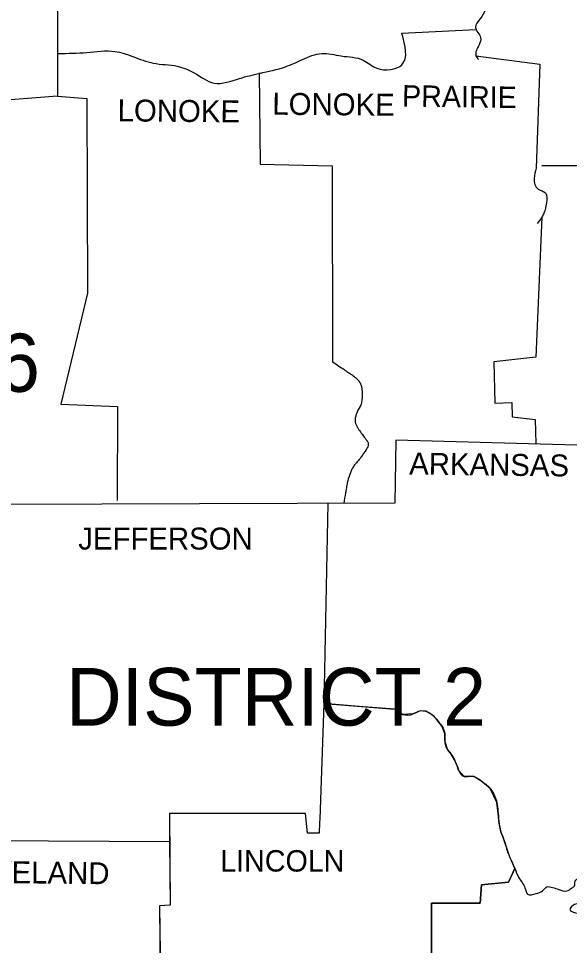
# Model space of a CAD drawing. Extents: x -31696 to 27919, y -8775 to 11152.
# Drawn here: x 13726 to 14782, y 6429 to 8206 of the extents above; entities that cross this region are included whole.
import ezdxf

# ---------------------------------------------------------------- set-up
doc = ezdxf.new("R2010")
doc.units = 0
for name, color, linetype in [('Level 1', 7, 'Continuous'), ('Level 2', 7, 'Continuous'), ('Level 3', 7, 'Continuous'), ('Level 48', 7, 'Continuous')]:
    doc.layers.add(name, color=color, linetype=linetype)

msp = doc.modelspace()

# ---------------------------------------------------------------- linework, layer by layer
at = {"layer": 'Level 1'}
for points in [[(13735.5, 10291.4), (13737.5, 10058.6), (13720.8, 10057.6), (13723.8, 9814), (13655.3, 9804.2), (13661.2, 9738.6), (13684.6, 9708.3), (13682.7, 9631), (13549.6, 9626.1), (13544.7, 9506.8), (13423.4, 9502.9), (13417.5, 9358), (13424.4, 9346.3), (13427.3, 9115.4), (13636.7, 9101.7), (13633.8, 8586.1), (13800.1, 8581.2), (13800.1, 8056.8), (13669, 8047), (13659.2, 7931.5), (13439.1, 7930.6)], [(15103.3, 8597.8), (15118, 8061.7), (14885.1, 8060.7), (14884.2, 8039.2), (14816.7, 8035.2), (14810.8, 7923.7), (14728.6, 7923.7)], [(14460.5, 8178.1), (14602.4, 8184.9)], [(14602.4, 8134.1), (14724.7, 8118.4), (14717.8, 7918.8)], [(14186.6, 8101.8), (14188.5, 7926.6), (14326.5, 7923.7), (14327.4, 7548)], [(13800.1, 8056.8), (13856.8, 8052.9), (13857.8, 7679.1), (13806.9, 7466.8), (13915.5, 7461.9), (13914.6, 7281.9)], [(14728.6, 7824.9), (14716.9, 7556.8), (14636.6, 7548), (14638.6, 7468.7), (14670.9, 7469.7), (14671.8, 7442.3), (14715.9, 7437.4), (14717.3, 7390.9)], [(14818.6, 7387.5), (14448.8, 7397.3), (14446.8, 7277), (13698.3, 7274)], [(14318.8, 7276.5), (14310.8, 6892.5), (14446.8, 6881.7)], [(14310.8, 6892.5), (14303, 6671.2)], [(14302.7, 6664.6), (14302, 6643.9), (14279.5, 6643.9), (14275.6, 6682.1), (14015.3, 6682.1), (14015.3, 6627.3)], [(13667, 6630.3), (14015.3, 6628.3)], [(14015.3, 6628.3), (14016.3, 6506), (13995.8, 6505), (14001.6, 6099)], [(14676.7, 6576.4), (14665, 6550), (14613.1, 6545.1), (14610.2, 6509.9), (14517.3, 6509.9), (14516.3, 6217.4)]]:
    msp.add_lwpolyline(points, dxfattribs=at)
for points in [[(14726.6, 8711.3), (14721.7, 8679), (14703.2, 8670.2), (14681.6, 8648.7), (14676.7, 8629.1), (14659.1, 8621.3), (14642.5, 8600.8), (14631.7, 8572.4), (14631.7, 8543), (14638.6, 8509.8), (14663, 8501), (14674.8, 8481.4), (14672.8, 8460.8), (14696.3, 8447.2), (14700.2, 8435.4), (14696.3, 8422.7), (14685.5, 8386.5), (14686.5, 8362), (14684.6, 8351.3), (14658.2, 8344.4), (14642.5, 8318), (14631.7, 8299.4), (14627.8, 8275), (14630.8, 8257.3), (14622.9, 8243.6), (14620, 8223.1), (14610.2, 8205.5), (14601.4, 8188.9), (14611.2, 8169.3), (14608.3, 8155.6), (14602.4, 8134.1), (14607.3, 8127.2)], [(13802, 8139), (13856.8, 8140.9), (13910.6, 8142.9), (13944.9, 8133.1), (13984, 8120.4), (14030, 8114.5), (14062.3, 8101.8), (14100.5, 8082.2), (14149.4, 8091), (14187.5, 8100.8), (14237.4, 8113.5), (14269.7, 8127.2), (14306.9, 8139), (14344.1, 8134.1), (14386.2, 8126.2), (14412.6, 8110.6), (14460.5, 8117.4), (14460.5, 8178.1)], [(14717.8, 7918.8), (14713.9, 7899.2), (14721.7, 7878.7), (14735.4, 7871.8), (14737.4, 7852.3), (14732.5, 7832.7), (14728.6, 7824.9), (14719.8, 7813.1)], [(14327.4, 7548), (14351.9, 7531.4), (14358.5, 7527), (14365, 7522.7), (14371.3, 7517.8), (14374.3, 7515), (14375.8, 7513.4), (14377.3, 7511.8), (14381.2, 7505.7), (14383.2, 7499.1), (14384, 7492.2), (14384.1, 7488.8), (14384.2, 7485.4), (14384.2, 7480.7), (14383.9, 7476), (14383.3, 7471.4), (14382.2, 7466.8), (14380.6, 7462.7), (14378.4, 7458.9), (14376.2, 7455.1), (14374.4, 7451.1), (14372.4, 7445.1), (14370.9, 7438.7), (14372.5, 7426.7), (14373.8, 7424.4), (14375.2, 7422.2), (14378.1, 7417.7), (14384.2, 7409.1), (14386.9, 7405.4), (14389.8, 7401.7), (14393.8, 7396.3), (14394.4, 7395.3), (14395, 7394.4), (14395.9, 7388.1), (14393.2, 7381.3), (14388.7, 7374.5), (14386.4, 7371.2), (14384.2, 7368), (14382, 7364.7), (14379.5, 7361.7), (14374.5, 7355.9), (14369.7, 7350), (14367.5, 7346.9), (14365.6, 7343.5), (14362.5, 7336.9), (14359.7, 7330.1), (14355.8, 7316.1), (14354, 7306.2), (14352.3, 7296.4), (14349.2, 7276.6)], [(14446.8, 6881.7), (14461.5, 6871.9), (14482, 6872.9), (14495.7, 6878.8), (14506.5, 6877.8), (14521.2, 6869), (14531, 6857.2), (14537.8, 6848.4), (14542.7, 6834.7), (14542.7, 6822), (14547.6, 6804.4), (14553.5, 6797.6), (14561.3, 6784.8), (14566.2, 6773.1), (14569.1, 6765.3), (14579.9, 6752.6), (14589.7, 6753.5), (14598.5, 6752.6), (14610.2, 6745.7), (14627.8, 6732), (14630.8, 6728.1), (14642.5, 6702.7), (14644.5, 6687), (14646.4, 6666.5), (14650.3, 6646.9), (14658.2, 6625.4), (14662.1, 6610.7), (14670.9, 6590.1), (14676.7, 6576.4), (14684.6, 6558.8), (14696.3, 6539.3), (14701.2, 6527.5), (14717.8, 6528.5), (14729.6, 6533.4), (14738.4, 6541.2), (14749.1, 6540.2), (14760.9, 6536.3), (14776.5, 6533.4), (14786.3, 6539.3), (14791.2, 6543.2), (14792.2, 6552), (14801, 6556.9), (14810.8, 6550), (14821.5, 6534.4), (14821.5, 6524.6), (14817.6, 6518.7), (14804.9, 6510.9), (14787.3, 6505), (14782.4, 6498.2), (14799, 6490.3), (14825.5, 6488.4), (14832.3, 6494.3), (14849.9, 6489.4), (14856.8, 6494.3), (14880.2, 6493.3), (14891, 6501.1), (14912.5, 6500.1), (14919.4, 6495.2), (14919.4, 6486.4), (14937, 6482.5), (14949.7, 6485.4), (14966.3, 6480.6), (14981, 6472.7), (14988.9, 6462), (14998.6, 6450.2), (15007.4, 6453.2), (15014.3, 6462), (15029, 6477.6), (15029, 6487.4), (15032.9, 6494.3), (15037.8, 6504)]]:
    msp.add_spline(points, degree=3, dxfattribs=at)
at = {"layer": 'Level 48'}
msp.add_lwpolyline([(14516.3, 6217.4), (14517.3, 6509.9), (14610.2, 6509.9), (14613.1, 6545.1), (14665, 6550), (14676.7, 6576.4), (14666.5, 6600.4), (14654.2, 6636.1), (14650.3, 6646.9), (14648.4, 6656.7), (14646.4, 6666.5), (14645.4, 6676.7), (14644.5, 6687), (14642.5, 6702.7), (14636.6, 6715.4), (14629.3, 6730), (14619, 6738.9), (14610.2, 6745.7), (14598.5, 6752.6), (14594.1, 6753), (14589.7, 6753.5), (14584.8, 6753), (14579.9, 6752.6), (14574.5, 6758.9), (14569.1, 6765.3), (14566.2, 6773.1), (14561.3, 6784.8), (14553.5, 6797.6), (14547.6, 6804.4), (14542.7, 6822), (14542.7, 6828.4), (14542.7, 6834.7), (14540.3, 6841.6), (14537.8, 6848.4), (14531, 6857.2), (14526.1, 6863.1), (14521.2, 6869), (14513.8, 6873.4), (14506.5, 6877.8), (14495.7, 6878.8), (14482, 6872.9), (14471.8, 6872.4), (14461.5, 6871.9), (14454.2, 6876.8), (14446.8, 6881.7), (14378.8, 6887.1), (14310.8, 6892.5), (14303, 6671.2), (14302.7, 6664.6), (14302, 6643.9), (14279.5, 6643.9), (14275.6, 6682.1), (14145.5, 6682.1), (14015.3, 6682.1), (14016.3, 6506), (13995.8, 6505), (13998.7, 6232)], dxfattribs=at)
msp.add_lwpolyline([(14516.3, 6217.4), (14517.3, 6509.9), (14610.2, 6509.9), (14613.1, 6545.1), (14665, 6550), (14676.7, 6576.4), (14666.5, 6600.4), (14654.2, 6636.1), (14650.3, 6646.9), (14648.4, 6656.7), (14646.4, 6666.5), (14645.4, 6676.7), (14644.5, 6687), (14642.5, 6702.7), (14636.6, 6715.4), (14629.3, 6730), (14619, 6738.9), (14610.2, 6745.7), (14598.5, 6752.6), (14594.1, 6753), (14589.7, 6753.5), (14584.8, 6753), (14579.9, 6752.6), (14574.5, 6758.9), (14569.1, 6765.3), (14566.2, 6773.1), (14561.3, 6784.8), (14553.5, 6797.6), (14547.6, 6804.4), (14542.7, 6822), (14542.7, 6828.4), (14542.7, 6834.7), (14540.3, 6841.6), (14537.8, 6848.4), (14531, 6857.2), (14526.1, 6863.1), (14521.2, 6869), (14513.8, 6873.4), (14506.5, 6877.8), (14495.7, 6878.8), (14482, 6872.9), (14471.8, 6872.4), (14461.5, 6871.9), (14454.2, 6876.8), (14446.8, 6881.7), (14378.8, 6887.1), (14310.8, 6892.5), (14303, 6671.2), (14302.7, 6664.6), (14302, 6643.9), (14279.5, 6643.9), (14275.6, 6682.1), (14145.5, 6682.1), (14015.3, 6682.1), (14016.3, 6506), (13995.8, 6505), (13998.7, 6232)], dxfattribs=at)

# ---------------------------------------------------------------- texts
at = {"layer": 'Level 2'}
for s, height, rotation, p in [('PRAIRIE', 41.09, 359.2116, (14460.5, 8037.2)), ('LONOKE', 42.07, 359.4974, (13915.5, 8008.8)), ('LONOKE', 42.07, 359.4974, (14212, 8021.5)), ('ARKANSAS', 42.06, 359.2678, (14474.2, 7331.8)), ('CLEVELAND', 42.07, 359.3377, (13565.3, 6550))]:
    msp.add_text(s, height=height, rotation=rotation, dxfattribs=at).set_placement(p)
for s, height, p in [('JEFFERSON', 42.07, (13840.2, 7187.9)), ('LINCOLN', 41.09, (14112.2, 6570.6))]:
    msp.add_text(s, height=height, dxfattribs=at).set_placement(p)
at = {"layer": 'Level 3'}
for s, height, p in [('DISTRICT 6', 111.54, (12954.7, 7490.3)), ('DISTRICT 2', 110.56, (13816.7, 6850.4))]:
    msp.add_text(s, height=height, dxfattribs=at).set_placement(p)

doc.saveas('drawing.dxf')
